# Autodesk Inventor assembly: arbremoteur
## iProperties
Shininess: 64.0
Length Units: 11269
Angle Units: 11279
Time Units: 11290
Mass Units: 11283
Length Display Precision: 3
Angle Display Precision: 2
Compacted: True
Created: 2006-01
Part Number: arbremoteur
Document SubType Name: Assembly
Designer: riri
Density: 0.0
Volumn: 0.0
Area: 0.0
PropertySet Name: Model Information
Control State: 0
Master: False
Checked Out: False
Author: riri
